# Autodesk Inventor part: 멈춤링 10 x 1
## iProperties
IsCustomPart: 0
Created: 2009-02
Part Number: 멈춤링 10 x 1
Material: Steel, Mild
Description: 리테이닝 링(C형)
Document SubType Name: Modeling
Standard: KS B 1336
Designer: SeoGD™
Standards Organization: KS
Language: ko-KR
Size Designation: 10 x 1
Categories: <MemberInstance><Categories><Category DisplayName="샤프트 부품" InternalName="7f7aeb1f-a693-4053-b835-cee3144e0d98" Mnemonic="SHFT"><Category DisplayName="써클립" Inter
Density: 1 g/cm^3
Author: SeoGD™
